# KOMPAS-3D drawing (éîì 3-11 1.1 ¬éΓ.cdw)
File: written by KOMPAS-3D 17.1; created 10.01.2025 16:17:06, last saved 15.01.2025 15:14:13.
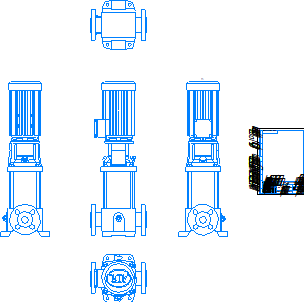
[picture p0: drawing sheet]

Sheet 1: A4, portrait

Title block, sheet 1: name: ВМН 3-11 1.1 кВт; designation: ВМН 3-11 1.1 кВт; material: Сталь 10  ГОСТ 1050-2013; mass: 68,16; sheets: 1; sheet format: A4; stored path: \\adlc.lan\data\АДЛ_ПКД\3D-модели\ADL production\Насосы ГРАНПАМП\Насосы ВМН\ВМН3\KOMPAS 3D\3-11 1.1 кВт _ ВМН.cdw

Views: Вид 1, Спереди, Проекционный вид 2, Проекционный вид 3, Проекционный вид 4, Проекционный вид 5
Referenced files in \\adlc.lan\data\АДЛ_ПКД\3D-модели\ADL production\Насосы ГРАНПАМП\Насосы ВМН\ВМН3\KOMPAS 3D\: ВМН 3-11 1.1 кВт.m3d
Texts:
  Andrey
  АДЛ
Dimensions and other numbers on the sheet: 1:1; 1; 68,16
